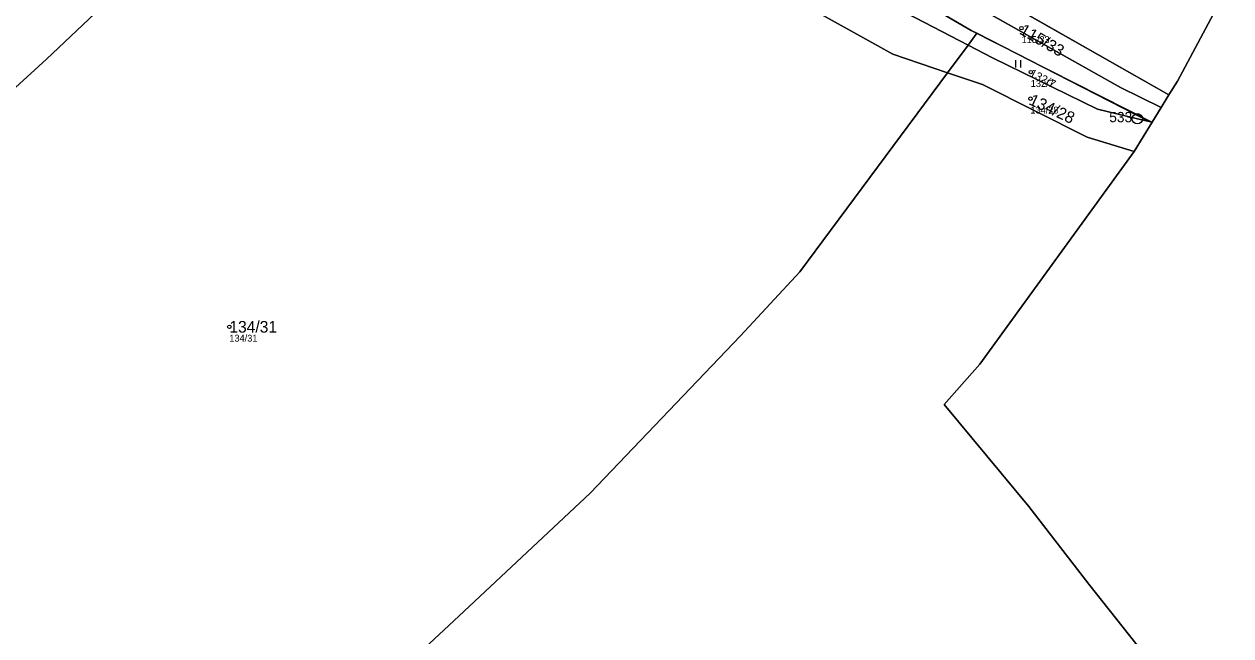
# Model space of a CAD drawing. Extents: x -734504 to -730695, y -1027923 to -1024502.
# Drawn here: x -731840.2 to -731664.3, y -1027012.7 to -1026923.5 of the extents above; entities that cross this region are included whole.
import ezdxf

# ---------------------------------------------------------------- set-up
doc = ezdxf.new("R2010")
doc.units = 0
for name, color, linetype in [('Definiční body', 7, 'Continuous'), ('Hranice parcel', 7, 'Continuous'), ('Parcelní čísla', 7, 'Continuous'), ('Polygon ku', 7, 'Continuous'), ('Polygon parcely', 7, 'Continuous'), ('Vnitřní kresba', 7, 'Continuous'), ('Značky bodu BP', 7, 'Continuous'), ('Značky kultur', 7, 'Continuous')]:
    doc.layers.add(name, color=color, linetype=linetype)

msp = doc.modelspace()

# ---------------------------------------------------------------- linework, layer by layer
at = {"layer": 'Definiční body'}
for centre in [(-731694.84, -1026924.12), (-731693.49, -1026930.52), (-731693.54, -1026934.4), (-731810.3, -1026967.66)]:
    msp.add_circle(centre, 0.25, dxfattribs=at)
at = {"layer": 'Hranice parcel'}
for p, q in [((-731673.35, -1026933.83), (-731707.6, -1026914.35)), ((-731680.41, -1026932.78), (-731709.72, -1026916.25)), ((-731666.5, -1026921.39), (-731672.12, -1026931.84)), ((-731702.64, -1026926.59), (-731701.36, -1026924.86)), ((-731701.36, -1026924.86), (-731676.25, -1026937.74)), ((-731705.62, -1026930.62), (-731702.64, -1026926.59)), ((-731674.5, -1026935.7), (-731680.41, -1026932.78)), ((-731672.12, -1026931.84), (-731673.35, -1026933.83)), ((-731673.35, -1026933.83), (-731674.5, -1026935.7)), ((-731674.5, -1026935.7), (-731675.82, -1026937.84)), ((-731675.82, -1026937.84), (-731678.44, -1026942.11)), ((-731676.25, -1026937.74), (-731675.82, -1026937.84)), ((-731678.44, -1026942.11), (-731685.28, -1026939.99)), ((-731678.44, -1026942.11), (-731700.94, -1026973.11)), ((-731700.94, -1026973.11), (-731706.14, -1026978.98))]:
    msp.add_line(p, q, dxfattribs=at)
for points in [[(-731785.24, -1026875.01), (-731742.3, -1026900.94), (-731702.17, -1026924.44), (-731701.36, -1026924.86)], [(-731702.64, -1026926.59), (-731711.61, -1026921.92), (-731723.82, -1026914.16), (-731734.87, -1026907.17), (-731760.24, -1026893.46), (-731787.82, -1026877.81)], [(-731920.64, -1026997.93), (-731903.28, -1026984.48), (-731871.99, -1026960.6), (-731836.93, -1026928.63), (-731804.3, -1026897.72), (-731789.8, -1026880.07)], [(-731789.8, -1026880.07), (-731762.44, -1026897.1), (-731738.24, -1026911.73), (-731726.8, -1026920.56), (-731713.61, -1026927.92), (-731705.62, -1026930.62)], [(-731702.64, -1026926.59), (-731699.09, -1026928.43), (-731683.78, -1026935.92), (-731677.96, -1026937.33), (-731676.25, -1026937.74)], [(-731705.62, -1026930.62), (-731727.13, -1026959.65), (-731735.8, -1026968.97), (-731757.73, -1026991.92), (-731776.85, -1027009.86), (-731799.78, -1027031.25)], [(-731685.28, -1026939.99), (-731700.55, -1026932.33), (-731705.62, -1026930.62)], [(-731706.14, -1026978.98), (-731693.77, -1026993.88), (-731685.03, -1027005.2), (-731668.15, -1027026.45)]]:
    msp.add_lwpolyline(points, dxfattribs=at)
at = {"layer": 'Polygon ku'}
msp.add_lwpolyline([(-731668.15, -1027026.45), (-731685.03, -1027005.2), (-731693.77, -1026993.88), (-731706.14, -1026978.98), (-731700.94, -1026973.11), (-731678.44, -1026942.11), (-731675.82, -1026937.84), (-731674.5, -1026935.7), (-731673.35, -1026933.83), (-731672.12, -1026931.84), (-731666.5, -1026921.39), (-731662.16, -1026913.85), (-731658.33, -1026907.21), (-731627.24, -1026908.72), (-731604.54, -1026909.94), (-731599.57, -1026910.3), (-731594.54, -1026910.67), (-731553.9, -1026913.9)], dxfattribs=at)
at = {"layer": 'Polygon parcely'}
for points in [[(-731804.3, -1026897.72), (-731789.8, -1026880.07), (-731795.17, -1026876.73), (-731811.52, -1026864.39), (-731827.17, -1026847.9), (-731836.7, -1026857.7), (-731851.85, -1026873.24), (-731856.11, -1026877.6), (-731858.22, -1026879.77), (-731864.98, -1026886.76), (-731867.81, -1026889.05), (-731870.05, -1026890.86), (-731886.99, -1026904.56), (-731902.61, -1026917.18), (-731908.98, -1026922.33), (-731950.5, -1026954.76), (-731933, -1026978.91), (-731920.64, -1026997.93), (-731903.28, -1026984.48), (-731871.99, -1026960.6), (-731836.93, -1026928.63)], [(-731780.29, -1026871.96), (-731785.24, -1026875.01), (-731742.3, -1026900.94), (-731702.17, -1026924.44), (-731701.36, -1026924.86), (-731676.25, -1026937.74), (-731675.82, -1026937.84), (-731674.5, -1026935.7), (-731680.41, -1026932.78), (-731709.72, -1026916.25), (-731723.35, -1026908.13), (-731740.74, -1026897.41), (-731753.18, -1026888.09)], [(-731701.36, -1026924.86), (-731702.17, -1026924.44), (-731742.3, -1026900.94), (-731785.24, -1026875.01), (-731787.82, -1026877.81), (-731760.24, -1026893.46), (-731734.87, -1026907.17), (-731723.82, -1026914.16), (-731711.61, -1026921.92), (-731702.64, -1026926.59)], [(-731726.8, -1026920.56), (-731713.61, -1026927.92), (-731705.62, -1026930.62), (-731702.64, -1026926.59), (-731711.61, -1026921.92), (-731723.82, -1026914.16), (-731734.87, -1026907.17), (-731760.24, -1026893.46), (-731787.82, -1026877.81), (-731789.8, -1026880.07), (-731762.44, -1026897.1), (-731738.24, -1026911.73)], [(-731823.58, -1027051.75), (-731799.78, -1027031.25), (-731776.85, -1027009.86), (-731757.73, -1026991.92), (-731735.8, -1026968.97), (-731727.13, -1026959.65), (-731705.62, -1026930.62), (-731713.61, -1026927.92), (-731726.8, -1026920.56), (-731738.24, -1026911.73), (-731762.44, -1026897.1), (-731789.8, -1026880.07), (-731804.3, -1026897.72), (-731836.93, -1026928.63), (-731871.99, -1026960.6), (-731903.28, -1026984.48), (-731920.64, -1026997.93), (-731920.31, -1026998.43), (-731905.11, -1027022.15), (-731891.17, -1027046.95), (-731869.78, -1027086.97), (-731867.94, -1027085.5), (-731846.19, -1027068.44)], [(-731666.5, -1026921.39), (-731690.77, -1026908.13), (-731696.92, -1026904.81), (-731707.6, -1026914.35), (-731673.35, -1026933.83), (-731672.12, -1026931.84)], [(-731673.35, -1026933.83), (-731707.6, -1026914.35), (-731709.72, -1026916.25), (-731680.41, -1026932.78), (-731674.5, -1026935.7)], [(-731683.78, -1026935.92), (-731677.96, -1026937.33), (-731676.25, -1026937.74), (-731701.36, -1026924.86), (-731702.64, -1026926.59), (-731699.09, -1026928.43)], [(-731678.44, -1026942.11), (-731675.82, -1026937.84), (-731676.25, -1026937.74), (-731677.96, -1026937.33), (-731683.78, -1026935.92), (-731699.09, -1026928.43), (-731702.64, -1026926.59), (-731705.62, -1026930.62), (-731700.55, -1026932.33), (-731685.28, -1026939.99)]]:
    msp.add_lwpolyline(points, close=True, dxfattribs=at)
msp.add_lwpolyline([(-731668.15, -1027026.45), (-731685.03, -1027005.2), (-731693.77, -1026993.88), (-731706.14, -1026978.98), (-731700.94, -1026973.11), (-731678.44, -1026942.11), (-731685.28, -1026939.99), (-731700.55, -1026932.33), (-731705.62, -1026930.62), (-731727.13, -1026959.65), (-731735.8, -1026968.97), (-731757.73, -1026991.92), (-731776.85, -1027009.86), (-731799.78, -1027031.25)], dxfattribs=at)
at = {"layer": 'Vnitřní kresba'}
msp.add_lwpolyline([(-731583.25, -1026737.15), (-731592.71, -1026767.25), (-731597.22, -1026778.21), (-731604.6, -1026786.97), (-731610.35, -1026803.3), (-731621.04, -1026811.26), (-731624.72, -1026819.91), (-731644.09, -1026834.02), (-731648.16, -1026839.75), (-731652.81, -1026856.67), (-731661.01, -1026868.45), (-731670.79, -1026877.48), (-731681.44, -1026887.8), (-731694.15, -1026903.22), (-731709.72, -1026916.25), (-731711.85, -1026918.77), (-731702.17, -1026924.44), (-731675.82, -1026937.84)], dxfattribs=at)
at = {"layer": 'Značky bodu BP'}
for radius in [0.75, 0.03]:
    msp.add_circle((-731677.96, -1026937.33), radius, dxfattribs=at)
at = {"layer": 'Značky kultur'}
for p, q in [((-731695.66, -1026929.84), (-731695.66, -1026928.79)), ((-731694.96, -1026929.84), (-731694.96, -1026928.79))]:
    msp.add_line(p, q, dxfattribs=at)

# ---------------------------------------------------------------- texts
at = {"layer": 'Definiční body'}
for s, p in [('115/33', (-731694.84, -1026926.28)), ('132/7', (-731693.49, -1026932.68)), ('134/28', (-731693.54, -1026936.56)), ('134/31', (-731810.3, -1026969.82))]:
    msp.add_text(s, height=1, dxfattribs=at).set_placement(p)
at = {"layer": 'Parcelní čísla'}
for s, height, rotation, p in [('115/33', 1.7, 330, (-731695.27, -1026924.86)), ('132/7', 1.19, 332, (-731693.77, -1026931.05)), ('134/28', 1.7, 335, (-731693.9, -1026935.17))]:
    msp.add_text(s, height=height, rotation=rotation, dxfattribs=at).set_placement(p)
msp.add_text('134/31', height=1.7, dxfattribs=at).set_placement((-731810.3, -1026968.51))
at = {"layer": 'Značky bodu BP'}
msp.add_text('533', height=1.5, dxfattribs=at).set_placement((-731682.06, -1026937.83))

doc.saveas('drawing.dxf')
